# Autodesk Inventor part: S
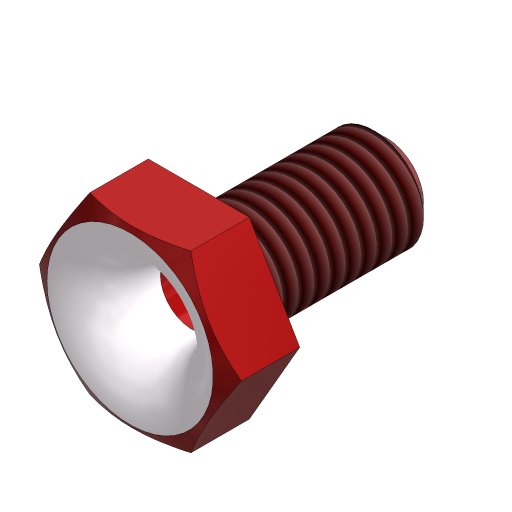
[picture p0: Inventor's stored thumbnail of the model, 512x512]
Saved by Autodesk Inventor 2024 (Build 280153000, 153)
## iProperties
Company: ATC
Shininess: 20.0
Length Units: 11269
Angle Units: 11279
Time Units: 11290
Mass Units: 11283
Length Display Precision: 3
Angle Display Precision: 2
Compacted: True
Created: 2023-03
Part Number: S
Document SubType Name: Modeling
Designer: Andrzej Jaskulski
Material: Kurs-AJ
Density: 1 g/cm^3
Appearance: Gładkie — czerwone
Checked By: A.J.
Engr Approved By: Andrzej Jaskulski
Mfg Approved By: Andrzej Jaskulski
Authority: A.J.
Density: 0.0
Volumn: 0.0
Area: 0.0
PropertySet Name: Model Information
Control State: 0
Master: False
Checked Out: False
Title: A.J.: Kurs R2024-MEP
Author: Andrzej Jaskulski
Revision Number: 1/24
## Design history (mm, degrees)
node "Extrusion1" dims "d1" = 15, "d2" = 0
workaxis "Work Axis3"
node "Chamfer1" dims "d6" = 1, "d7" = 1, "d51" = 45 deg
thread "Thread1" dims "d37" = 10, "d38" = 0
sketch "Sketch7"
  geometry: L1 (-4.041, 7)-(4.041, 7); L2 (4.041, 7)-(8.083, 0); L3 (8.083, 0)-(4.041, -7); L4 (4.041, -7)-(-4.041, -7); L5 (-4.041, -7)-(-8.083, 0); L6 (-8.083, 0)-(-4.041, 7); C1 r 5 at (0, 0); A1 r 8.083 centre (0, 0) between (-4.041, 7) and (4.041, 7); 1 further point
  constraints: 12 end point, 6 point on circle, 3 equal length, 2 centre point, 2 coincident, 2 parallel, 1 horizontal
  dimensions: "d40" = 14 distance between parallel lines of L4 L1
extrude "Extrusion5" join sketch "Sketch7" distance "d41" = 5.5; taper "d42" = 0 deg
workplane "Work Plane3"
revolve "Revolution1" stored, may be unused: angle "d44" = 90 deg
sketch "Sketch9"
  geometry: C1 r 6.65 at (0, 0) reference; C2 r 2.5 at (0, 0)
  constraints: 1 centre point, 1 coincident
  dimensions: "d47" = 5 diameter of C2
extrude "Extrusion6" cut sketch "Sketch9" extent not by distance; stored distance "d48" = 5.5; taper "d49" = 0 deg
fillet "Fillet1" dims "d50" = 5
node "Bryła1"
node "Korpusy bryłowe"
node "Korpusy powierzchniowe"
sketch "Sketch1"
  geometry: C1 r 4 at (0, 0)
  constraints: 1 centre point
  dimensions: "d0" = 8 diameter of C1
sketch "Sketch8"
  geometry: L1 (-8.083, -25.18)-(-8.083, 7.582) reference; L2 (-4.041, 0)-(-12.124, 0) reference; L3 (-1.433, 0)-(7.167, -4.965); L4 (7.167, -4.965)-(7.167, 2.902); L5 (0, -5.5)-(0, 0) reference; L6 (7.167, 2.902)-(-1.433, 2.902); L7 (-1.433, 0)-(-1.433, 2.902)
  constraints: 8 end point, 1 horizontal, 1 parallel, 1 perpendicular, 1 point on line
  dimensions: "d43" = 30 deg angle of L6 L3; "d46" = 6.65 distance between parallel lines of L7 L1
other parameters: "p" = 1.25 [user parameter], "de" = 8 [user parameter], "de1" = 6.647 [user parameter], "de2" = 7.188 [user parameter], "d39" = 16.2 (derived)
